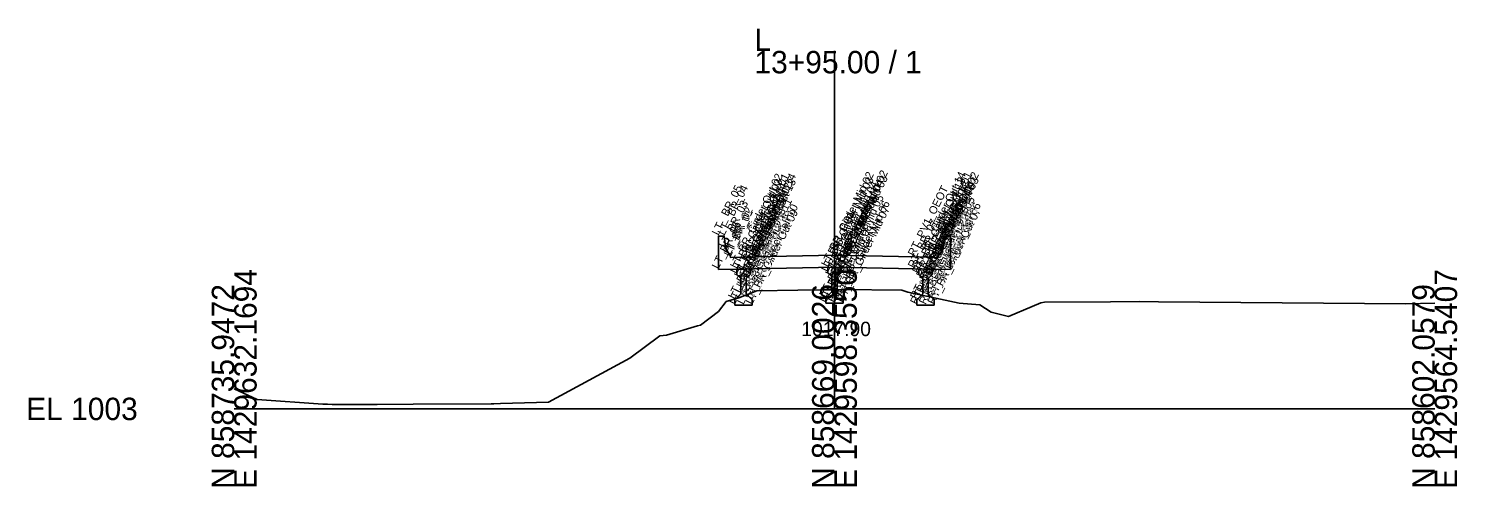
# Model space of a CAD drawing. Extents: x -26 to 2303, y -10 to 19558.
# Drawn here: x 1124.3 to 1302.8, y 13990.3 to 14047.5 of the extents above; entities that cross this region are included whole.
import ezdxf

# ---------------------------------------------------------------- set-up
doc = ezdxf.new("R2010")
doc.units = 0
for name, color, linetype in [('Default', 7, 'Continuous'), ('Exist Cross Section Cell', 7, 'Continuous'), ('Exist XS Center Line Elevation Label', 7, 'Continuous'), ('Exist XS Ground Line', 7, 'Continuous'), ('Prop CMT Concrete Structures', 7, 'Continuous'), ('Prop XS Dump Level', 7, 'Continuous')]:
    doc.layers.add(name, color=color, linetype=linetype)

msp = doc.modelspace()

# ---------------------------------------------------------------- linework, layer by layer
at = {"layer": 'Exist Cross Section Cell'}
for p, q in [((1225, 14000), (1225, 14044.75)), ((1150, 14000), (1225, 14000)), ((1225, 14000), (1300, 14000))]:
    msp.add_line(p, q, dxfattribs=at)
at = {"layer": 'Exist XS Ground Line'}
msp.add_lwpolyline([(1150, 14002.52), (1152.87, 14001.19), (1161.06, 14000.6), (1161.66, 14000.58), (1162.24, 14000.57), (1167.87, 14000.55), (1172.36, 14000.59), (1182.12, 14000.62), (1182.43, 14000.65), (1183.26, 14000.67), (1189.28, 14000.84), (1199.44, 14006.33), (1203.18, 14009.14), (1204.02, 14009.22), (1207.9, 14010.37), (1208.27, 14010.45), (1210.5, 14012.17), (1211.48, 14013.42), (1213.05, 14013.87), (1215.31, 14014.78), (1220.44, 14014.84), (1223.26, 14014.88), (1225, 14014.9), (1225.87, 14014.92), (1233.44, 14014.85), (1234.18, 14014.61), (1240.6, 14013.22), (1243.17, 14013.01), (1244.57, 14012.1), (1246.76, 14011.54), (1249.72, 14012.8), (1250.8, 14013.28), (1251.26, 14013.35), (1259.51, 14013.4), (1263.16, 14013.42), (1265.51, 14013.4), (1296.4, 14013.14), (1300, 14013.23)], dxfattribs=at)
at = {"layer": 'Prop CMT Concrete Structures'}
for points in [[(1225, 14019.2), (1215, 14019), (1212, 14018.94), (1211.99, 14019.19), (1211.41, 14020.02), (1211.24, 14021.61), (1210.5, 14021.61), (1210.5, 14017.41)], [(1225, 14019.2), (1235, 14019), (1238, 14018.94), (1238.01, 14019.19), (1238.59, 14020.02), (1238.76, 14021.61), (1239.5, 14021.61), (1239.5, 14017.41)], [(1225, 14017.7), (1225, 14019.2)], [(1225, 14017.7), (1225, 14019.2)], [(1210.5, 14017.41), (1215, 14017.5), (1225, 14017.7)], [(1214.46, 14017.49), (1213.62, 14017.47), (1212.79, 14017.46)], [(1212.79, 14017.46), (1212.79, 14016.81)], [(1212.79, 14016.81), (1213.29, 14016.31)], [(1213.96, 14016.31), (1214.46, 14016.81)], [(1214.46, 14016.81), (1214.46, 14017.49)], [(1225, 14017.7), (1224.17, 14017.68)], [(1224.17, 14017.68), (1224.17, 14017.03)], [(1224.17, 14017.03), (1224.67, 14016.53)], [(1225, 14013.2), (1225, 14017.7)], [(1225, 14017.7), (1225.83, 14017.68)], [(1225, 14013.2), (1225, 14017.7)], [(1239.5, 14017.41), (1235, 14017.5), (1225, 14017.7)], [(1225.83, 14017.03), (1225.33, 14016.53)], [(1225.83, 14017.68), (1225.83, 14017.03)], [(1235.54, 14017.49), (1236.38, 14017.47), (1237.21, 14017.46)], [(1235.54, 14016.81), (1235.54, 14017.49)], [(1236.04, 14016.31), (1235.54, 14016.81)], [(1237.21, 14016.81), (1236.71, 14016.31)], [(1237.21, 14017.46), (1237.21, 14016.81)], [(1213.29, 14016.31), (1213.29, 14014.39)], [(1213.96, 14014.39), (1213.96, 14016.31)], [(1224.67, 14016.53), (1224.67, 14014.62)], [(1225.33, 14016.53), (1225.33, 14014.62)], [(1236.04, 14014.39), (1236.04, 14016.31)], [(1236.71, 14016.31), (1236.71, 14014.39)], [(1213.29, 14014.39), (1212.54, 14013.64)], [(1212.54, 14013.64), (1212.54, 14012.97)], [(1214.71, 14013.64), (1213.96, 14014.39)], [(1214.71, 14012.97), (1214.71, 14013.64)], [(1224.67, 14014.62), (1223.92, 14013.87)], [(1223.92, 14013.87), (1223.92, 14013.2)], [(1223.92, 14013.2), (1225, 14013.2)], [(1226.08, 14013.2), (1225, 14013.2)], [(1225.33, 14014.62), (1226.08, 14013.87)], [(1226.08, 14013.87), (1226.08, 14013.2)], [(1235.29, 14013.64), (1236.04, 14014.39)], [(1235.29, 14012.97), (1235.29, 14013.64)], [(1236.71, 14014.39), (1237.46, 14013.64)], [(1237.46, 14013.64), (1237.46, 14012.97)], [(1212.54, 14012.97), (1213.62, 14012.97), (1214.71, 14012.97)], [(1237.46, 14012.97), (1236.38, 14012.97), (1235.29, 14012.97)]]:
    msp.add_lwpolyline(points, dxfattribs=at)

# ---------------------------------------------------------------- texts
at = {"layer": 'Default'}
msp.add_text('-', height=0.0001, dxfattribs=at).set_placement((1150, 14000))
at = {"layer": 'Exist Cross Section Cell'}
for s, p in [('L', (1215, 14044.75)), ('13+95.00 / 1', (1215, 14041.95)), ('EL 1003', (1124, 13998.6))]:
    msp.add_text(s, height=2.8, dxfattribs=at).set_placement(p)
for s, p in [('E 1429632.1694', (1152.8, 13990)), ('E 1429598.3550', (1227.8, 13990)), ('E 1429564.5407', (1302.8, 13990)), ('N 858735.9472', (1150, 13990)), ('N 858669.0026', (1225, 13990)), ('N 858602.0579', (1300, 13990))]:
    msp.add_text(s, height=2.8, rotation=90, dxfattribs=at).set_placement(p)
at = {"layer": 'Exist XS Center Line Elevation Label'}
msp.add_text('1017.90', height=1.8, dxfattribs=at).set_placement((1220.86, 14009.1))
at = {"layer": 'Prop XS Dump Level'}
for s, p in [('LT_BR_Girder Out 02', (1212.79, 14017.46)), ('LT_BR_Girder Out 01', (1213.62, 14017.47)), ('LT_BR_Girder Out 14', (1214.46, 14017.49)), ('LT_BR_Girder Mid 02', (1224.17, 14017.68)), ('RT_BR_Girder Mid 02', (1225.83, 14017.68)), ('RT_BR_Girder Mid 03', (1225.83, 14017.03)), ('RT_BR_Girder Out 14', (1235.54, 14017.49)), ('RT_BR_Girder Out 01', (1236.38, 14017.47)), ('RT_BR_Girder Out 02', (1237.21, 14017.46)), ('LT_ BR_05', (1210.5, 14021.61)), ('LT_ BR_04', (1211.24, 14021.61)), ('LT_BR_Girder Out 03', (1212.79, 14016.81)), ('LT_BR_Girder Out 04', (1213.29, 14016.31)), ('LT_BR_Girder Out 12', (1213.96, 14016.31)), ('LT_BR_Girder Out 13', (1214.46, 14016.81)), ('LT_PV1_OEOT', (1215, 14019)), ('LT_BR_Girder Mid 03', (1224.17, 14017.03)), ('LT_BR_Girder Mid 04', (1224.67, 14016.53)), ('RT_BR_Girder Mid 04', (1225.33, 14016.53)), ('RT_PV1_OEOT', (1235, 14019)), ('RT_BR_Girder Out 13', (1235.54, 14016.81)), ('RT_BR_Girder Out 12', (1236.04, 14016.31)), ('RT_BR_Girder Out 04', (1236.71, 14016.31)), ('RT_BR_Girder Out 03', (1237.21, 14016.81)), ('RT_ BR_04', (1238.76, 14021.61)), ('RT_ BR_05', (1239.5, 14021.61)), ('LT_BR_03', (1211.41, 14020.02)), ('LT_BR_Girder Out 06', (1212.54, 14013.64)), ('LT_BR_Girder Out 05', (1213.29, 14014.39)), ('LT_BR_Girder Out 11', (1213.96, 14014.39)), ('LT_BR_Girder Out 10', (1214.71, 14013.64)), ('LT_BR_Girder Mid 06', (1223.92, 14013.87)), ('LT_BR_Girder Mid 05', (1224.67, 14014.62)), ('RT_BR_Girder Mid 05', (1225.33, 14014.62)), ('RT_BR_Girder Mid 06', (1226.08, 14013.87)), ('RT_BR_Girder Out 10', (1235.29, 14013.64)), ('RT_BR_Girder Out 11', (1236.04, 14014.39)), ('RT_BR_Girder Out 05', (1236.71, 14014.39)), ('RT_BR_Girder Out 06', (1237.46, 14013.64)), ('RT_BR_03', (1238.59, 14020.02)), ('LT_BR_02', (1211.99, 14019.19)), ('LT_BR_01', (1212, 14018.94)), ('LT_BR_Girder Out 07', (1212.54, 14012.97)), ('LT_BR_Girder Out 08', (1213.62, 14012.97)), ('LT_BR_Girder Out 09', (1214.71, 14012.97)), ('LT_BR_Girder Mid 07', (1223.92, 14013.2)), ('PV1_PGL', (1225, 14019.2)), ('RT_BR_Girder Mid 07', (1226.08, 14013.2)), ('RT_BR_07', (1235, 14017.5)), ('RT_BR_Girder Out 09', (1235.29, 14012.97)), ('RT_BR_Girder Out 08', (1236.38, 14012.97)), ('RT_BR_Girder Out 07', (1237.46, 14012.97)), ('RT_BR_01', (1238, 14018.94)), ('RT_BR_02', (1238.01, 14019.19)), ('LT_BR_06', (1210.5, 14017.41)), ('LT_BR_07', (1215, 14017.5)), ('BR_Girder Mid 08', (1225, 14013.2)), ('BR_PGL', (1225, 14017.7)), ('RT_BR_06', (1239.5, 14017.41))]:
    msp.add_text(s, height=1, rotation=63.5833, dxfattribs=at).set_placement(p)

doc.saveas('drawing.dxf')
